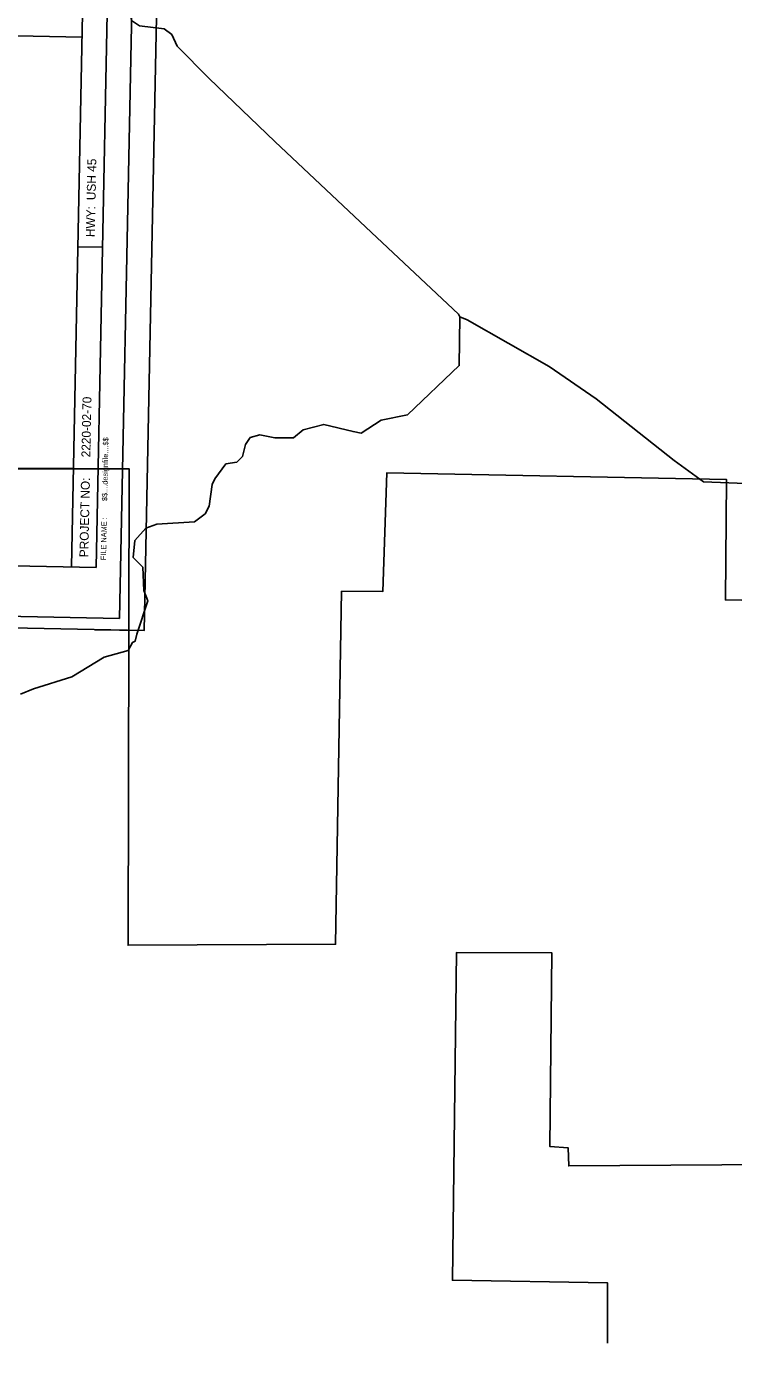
# Model space of a CAD drawing. Extents: x 331323 to 388339, y 121519 to 205315.
# Drawn here: x 366558 to 375161, y 121519 to 137621 of the extents above; entities that cross this region are included whole.
import ezdxf

# ---------------------------------------------------------------- set-up
doc = ezdxf.new("R2010")
doc.units = 0
for name, color, linetype in [('Level 21', 7, 'Continuous'), ('Level 4', 7, 'Continuous'), ('Level 57', 7, 'Continuous'), ('P_RDWY_Text', 7, 'Continuous'), ('PLT_Sheet_Border', 7, 'Continuous'), ('PLT_Sheet_Info', 7, 'Continuous')]:
    doc.layers.add(name, color=color, linetype=linetype)

msp = doc.modelspace()

# ---------------------------------------------------------------- linework, layer by layer
at = {"layer": 'Level 21'}
for points in [[(377063, 130598), (375063, 130636), (375076, 132102), (370943, 132185), (370895, 130740), (370392, 130742), (370319, 126443), (367795, 126431), (367808, 132231), (366120, 132233), (366136, 131513), (366392, 131512), (366390, 130783), (366031, 131091), (365085, 131112), (365090, 131495), (364323, 131507), (364297, 130440), (364589, 130440), (364573, 129673), (363929, 129678), (363912, 128375), (362626, 128410), (362594, 121807)], [(373627, 121585), (373626, 122321), (371741, 122350), (371792, 126343), (372951, 126337), (372927, 123979), (373147, 123965), (373155, 123744), (376259, 123765), (376259, 123923), (376481, 123924), (376480, 123673), (376361, 123676), (376356, 123482), (376520, 123475), (376526, 123697), (376586, 123696), (376590, 123384), (376923, 123375), (376912, 121519)]]:
    msp.add_lwpolyline(points, dxfattribs=at)
at = {"layer": 'Level 4'}
for points in [[(358426, 137554), (363663, 137565), (367234, 137492)], [(363948, 132237), (367128, 132236)]]:
    msp.add_lwpolyline(points, dxfattribs=at)
at = {"layer": 'Level 57'}
for points in [[(366907, 140244), (366940, 140211), (366955, 140052), (366988, 139985), (367035, 139685), (367214, 139108), (367237, 138900), (367318, 138699), (367417, 138556), (367681, 138270), (367771, 138086), (367834, 137694), (367934, 137627), (368234, 137590), (368325, 137523), (368390, 137381), (368779, 136986), (369580, 136220), (370688, 135177), (371813, 134116), (371829, 134083)], [(366483, 129489), (366642, 129555), (367110, 129700), (367504, 129939), (367797, 130019), (367848, 130119), (367881, 130135), (367899, 130218), (368036, 130625), (367987, 130751), (367973, 131034), (367857, 131152), (367876, 131360), (368011, 131509), (368145, 131558), (368604, 131587), (368730, 131686), (368781, 131777), (368816, 132043), (368850, 132110), (368985, 132292), (369119, 132316), (369186, 132382), (369221, 132531), (369280, 132614), (369397, 132646), (369580, 132611), (369806, 132609), (369923, 132708), (370174, 132773), (370532, 132686), (370632, 132669), (370875, 132825), (371193, 132889), (371824, 133491), (371829, 134083)], [(371829, 134083), (371921, 134049), (372916, 133481), (373488, 133084), (374440, 132334), (374796, 132073), (378189, 131942)]]:
    msp.add_lwpolyline(points, dxfattribs=at)
at = {"layer": 'P_RDWY_Text'}
msp.add_lwpolyline([(354791, 130528), (355202, 150924), (368399, 150658), (367988, 130262)], close=True, dxfattribs=at)
at = {"layer": 'PLT_Sheet_Border'}
for points in [[(367988, 130262), (368399, 150658), (355202, 150924), (354791, 130528)], [(367691, 130412), (368091, 150268), (355494, 150522), (355094, 130666)]]:
    msp.add_lwpolyline(points, close=True, dxfattribs=at)
at = {"layer": 'PLT_Sheet_Info'}
for p, q in [((367104, 131039), (367484, 149935)), ((367404, 131033), (367784, 149929)), ((367482, 134932), (367182, 134938)), ((367404, 131033), (355406, 131274)), ((367988, 130262), (368000, 130862)), ((367988, 130262), (367388, 130274))]:
    msp.add_line(p, q, dxfattribs=at)

# ---------------------------------------------------------------- texts
for s, height, p in [('USH 45          ', 108, (367398, 135504)), ('HWY:', 108, (367388, 135054)), ('2220-02-70', 108, (367334, 132372)), ('$$....designfile....$$', 64.8, (367540, 131840)), ('PROJECT NO:', 108, (367310, 131155)), ('FILE NAME :', 64.8, (367525, 131120))]:
    msp.add_text(s, height=height, rotation=88.8462, dxfattribs=at).set_placement(p)

doc.saveas('drawing.dxf')
